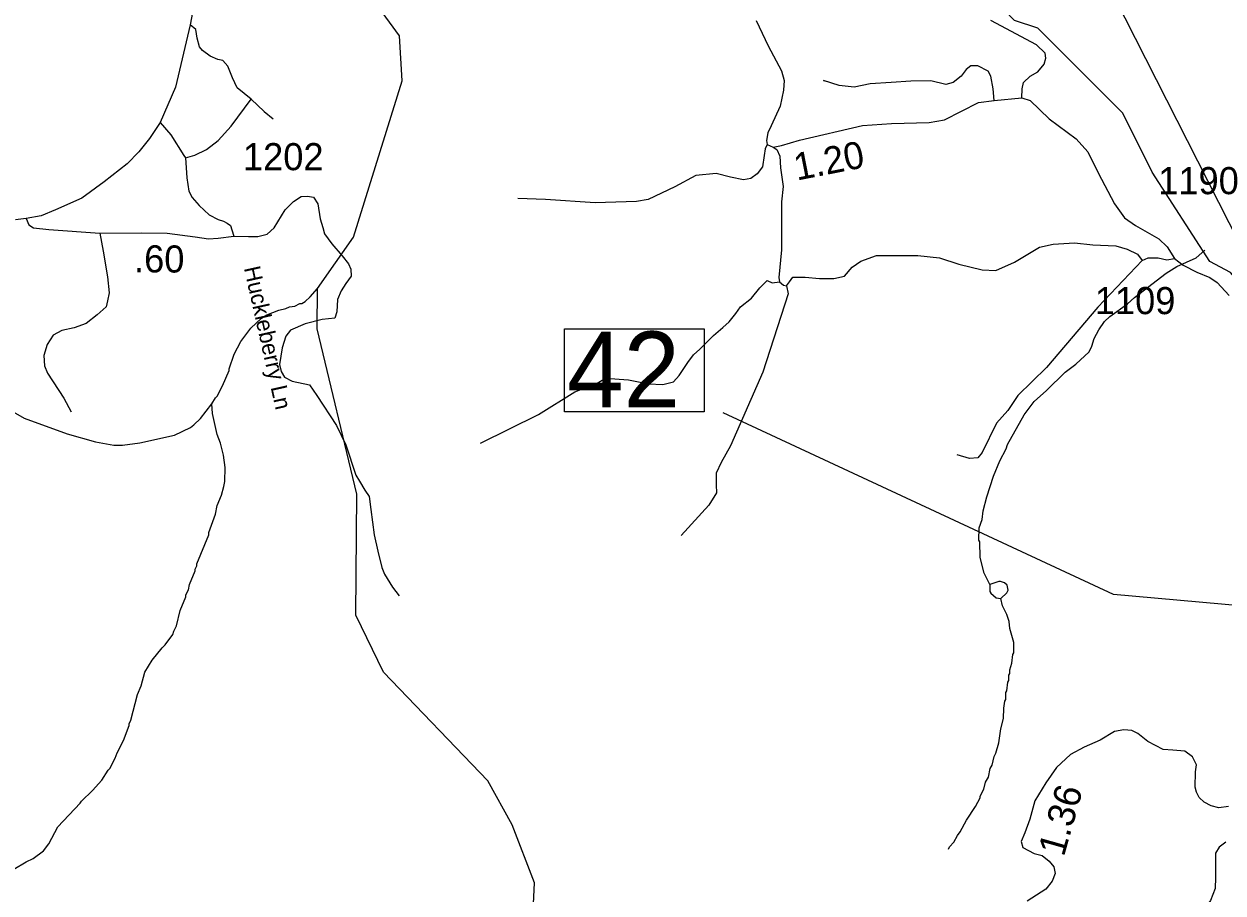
# Model space of a CAD drawing. Extents: x 1248224 to 1454986, y 825081 to 985870.
# Drawn here: x 1349562 to 1355092, y 850677 to 854684 of the extents above; entities that cross this region are included whole.
import ezdxf

# ---------------------------------------------------------------- set-up
doc = ezdxf.new("R2010")
doc.units = 0
for name, color, linetype in [('Exist Hydrographic Creek Single Shore', 7, 'Continuous'), ('Exist Hydrographic Misc Water Feature', 7, 'Continuous'), ('Exist Road Non-System Type 51', 7, 'Continuous'), ('Exist Road Secondary Mileage Hundredths English Label', 7, 'Continuous'), ('Exist Road Secondary Structure Standard Bridge Number Label', 7, 'Continuous'), ('Exist Road Secondary Type 41 Attributed', 7, 'Continuous'), ('Exist Road Secondary Type 51 Attributed', 7, 'Continuous'), ('Exist Road Secondary Type 51 Label', 7, 'Continuous'), ('Exist Road Secondary Type 51 Number Label', 7, 'Continuous')]:
    doc.layers.add(name, color=color, linetype=linetype)

msp = doc.modelspace()

# ---------------------------------------------------------------- linework, layer by layer
at = {"layer": 'Exist Hydrographic Creek Single Shore'}
msp.add_lwpolyline([(1355236.2, 853411.9), (1355127.2, 853537.3), (1355031.4, 853588.9), (1354765.5, 854001.3), (1354629.4, 854273.3), (1354237.4, 854665.2), (1354130.4, 854700.2), (1354081.4, 854750.4), (1354083.4, 854852.1), (1353903.4, 854990.3), (1353765.4, 855167.1), (1353601.4, 855305), (1353497.3, 855582.2), (1353427.9, 855911.2), (1353475.4, 856284.1), (1353588.6, 856393.7), (1353464.7, 856424.9), (1353212.7, 856728.3), (1352949.6, 857225.5), (1352872.2, 857635)], dxfattribs=at)
at = {"layer": 'Exist Hydrographic Misc Water Feature'}
for points in [[(1351884.4, 850047.6), (1351916.4, 850723.3), (1351813.4, 850991.2), (1351701.4, 851193.7), (1351220.4, 851695.8), (1351092.4, 851957.7), (1351096.4, 852515.7), (1350913.4, 853277.7), (1350915.1, 853464), (1351081.4, 853701.1), (1351305.3, 854422.1), (1351293.3, 854629.2), (1351034.4, 854985.6), (1350962.4, 855128.2), (1350783.4, 855309.1), (1350727.4, 855418.5), (1350737.3, 855526.7), (1350815.4, 855640.1), (1351146.3, 855899.3), (1351181.4, 855984), (1351097.3, 856350), (1351009.3, 856502.8), (1350790.3, 856776.4), (1350622.3, 857078.5)], [(1354015.9, 852099.1), (1353991.1, 852151.6), (1353972.7, 852224), (1353970.4, 852296.1), (1353966.6, 852304.2), (1353967.8, 852360.1), (1353980.7, 852399.8), (1353985.7, 852439.7), (1354003.1, 852503.3), (1354033.2, 852598.6), (1354062.9, 852669.8), (1354092.2, 852725.1), (1354098.5, 852745), (1354175.7, 852881.1), (1354221.2, 852944), (1354278.3, 852994.7), (1354364.2, 853078.6), (1354413.1, 853115.5), (1354474.4, 853171.9), (1354486.9, 853197.7), (1354497.8, 853233.4), (1354518.7, 853272.9), (1354545.6, 853312.2), (1354570.1, 853335.7), (1354651.5, 853393.7), (1354684.1, 853422.9), (1354830.7, 853535.4), (1354879.4, 853566.3), (1354968.4, 853606.1), (1355008.7, 853640.3)], [(1350427.4, 852932.2), (1350444.5, 852960), (1350452.7, 852967.8), (1350477.8, 853015.2), (1350507.5, 853086.4), (1350507.7, 853094.4), (1350531.2, 853161.9), (1350562.4, 853219.1), (1350607.9, 853282), (1350657, 853326.9), (1350681.3, 853342.3), (1350737.8, 853364.9), (1350769.9, 853372.2), (1350786.1, 853379.8), (1350810.2, 853383.2), (1350834.5, 853394.6), (1350842.5, 853394.4), (1350858.7, 853404.1), (1350881.2, 853425.5), (1350915.1, 853464)], [(1349142.7, 853012.3), (1349201.9, 853031.5), (1349243.9, 853032.6), (1349287.8, 853027.5), (1349333.4, 853010.4), (1349396.7, 852976.9), (1349471.4, 852919.1), (1349562.3, 852867), (1349760.7, 852794.3), (1349891.8, 852757.2), (1349975.5, 852741.2), (1350015.5, 852742.2), (1350095.7, 852752.3), (1350256.6, 852788.4), (1350329.4, 852822.7), (1350345.8, 852836.3), (1350376.4, 852865.6), (1350427.4, 852932.2)], [(1349515, 850786.4), (1349571.8, 850821), (1349604.2, 850836.2), (1349651.1, 850871.2), (1349675.8, 850904.5), (1349717.5, 850981.5), (1349820, 851091.1), (1349826.3, 851100.9), (1349877.3, 851149.7), (1349920.5, 851196.7), (1349949.5, 851244), (1349957.7, 851251.8), (1349982.8, 851299.2), (1349991.4, 851323), (1350020.7, 851380.2), (1350046.2, 851449.7), (1350046.4, 851457.7), (1350054.8, 851473.4), (1350085.5, 851592.7), (1350102.4, 851632.3), (1350119.8, 851695.9), (1350153.1, 851751.1), (1350198.4, 851808), (1350212.7, 851821.6), (1350247.8, 851868.8), (1350252.2, 851884.7), (1350264.7, 851908.4), (1350282.3, 851980), (1350307.7, 852043.3), (1350308, 852051.3), (1350320.5, 852075), (1350325, 852098.9), (1350350.5, 852162.3), (1350350.6, 852170.3), (1350359, 852186.1), (1350359.2, 852194.1), (1350414.3, 852328.8), (1350414.5, 852338.8), (1350444.4, 852424), (1350453.3, 852463.8), (1350472.4, 852511.4), (1350483.3, 852551.1), (1350487.9, 852575), (1350489.3, 852639), (1350482.6, 852695.1), (1350467.8, 852751.4), (1350452.7, 852791.8), (1350430.9, 852888.3), (1350427.4, 852932.2)], [(1354067.7, 852035), (1354095.1, 852061.1), (1354101.3, 852073), (1354095.9, 852097.1), (1354084.1, 852107.4), (1354066.3, 852113.8), (1354058.3, 852114), (1354015.9, 852099.1)], [(1354015.9, 852099.1), (1354017.2, 852067), (1354021, 852058.9), (1354046.6, 852038.3), (1354067.7, 852035)], [(1353826.2, 850879.7), (1353830.4, 850889.6), (1353850.9, 850911.1), (1353867.7, 850942.7), (1353880.1, 850958.4), (1353909.3, 851013.7), (1353950.7, 851076.7), (1353971.6, 851116.2), (1353971.8, 851124.2), (1353988.5, 851155.8), (1353997.3, 851187.6), (1354009.8, 851211.3), (1354018.7, 851251.1), (1354027.1, 851266.9), (1354036, 851306.6), (1354044.3, 851322.4), (1354057.4, 851370.2), (1354066.9, 851433.9), (1354080, 851481.6), (1354081, 851529.5), (1354085.7, 851561.4), (1354089.9, 851569.3), (1354090.7, 851601.3), (1354094.9, 851609.2), (1354099.8, 851649.1), (1354104, 851657), (1354104.5, 851681), (1354108.7, 851688.9), (1354109.1, 851706.8), (1354117.7, 851736.6), (1354122.6, 851776.5), (1354126.8, 851784.4), (1354127.9, 851832.4), (1354109.4, 851896.8), (1354106.1, 851928.9), (1354094.9, 851961.2), (1354075.8, 852001.6), (1354067.7, 852035)]]:
    msp.add_lwpolyline(points, dxfattribs=at)
at = {"layer": 'Exist Road Non-System Type 51'}
for points in [[(1350609.3, 854337.4), (1350544.3, 854389.9), (1350523.7, 854435.6), (1350502, 854489.2), (1350478.1, 854515.5), (1350455.3, 854520.1), (1350419.9, 854536), (1350385.7, 854562.3), (1350370.9, 854577.8), (1350360.7, 854618.9), (1350353.8, 854657.7), (1350327.7, 854679.7)], [(1354164.3, 854343.9), (1354165.7, 854385.3), (1354171.5, 854414.1), (1354203.2, 854443), (1354237.8, 854463.2), (1354266.6, 854497.8), (1354275.2, 854526.7), (1354272.4, 854549.7), (1354232, 854587.2), (1354021.6, 854699.7)], [(1354036, 854331), (1354032.1, 854384.8), (1354020.6, 854442.5), (1354009.1, 854465.6), (1353961, 854490.6), (1353928.4, 854490.6), (1353907.2, 854473.3), (1353884.2, 854442.5), (1353847.6, 854413.7), (1353813, 854404.1), (1353743.9, 854421.4), (1353651.6, 854419.4), (1353561.3, 854413.7), (1353465.2, 854407.9), (1353390.3, 854392.5), (1353321.1, 854400.2), (1353250, 854423.3), (1353255.7, 854421.4)], [(1350307, 854066.2), (1350350.3, 854078.2), (1350403.9, 854105.6), (1350457.6, 854146.7), (1350516.9, 854213), (1350609.3, 854337.4)], [(1350609.3, 854337.4), (1350669.7, 854280.3), (1350710.8, 854247.2)], [(1350190.2, 854229.6), (1350238.5, 854172.4), (1350299, 854077.6), (1350307, 854066.2)], [(1352990.3, 854128.3), (1352980.3, 854107.6), (1352976.5, 854076.8), (1352968.8, 854024.9), (1352943.8, 853992.2), (1352915, 853971.1), (1352880.4, 853965.3), (1352820.8, 853976.8), (1352753.6, 853994.1), (1352661.3, 853984.5), (1352563.3, 853932.6), (1352440.3, 853874.9), (1352386.5, 853865.3), (1352196.2, 853859.5), (1351967.6, 853874.9), (1351839.3, 853878.8)], [(1353016.7, 854115.8), (1353034.2, 854105.7), (1353047.6, 854075), (1353051.5, 854021.1), (1353063, 853934.6), (1353055.3, 853863.4), (1353055.3, 853642.2), (1353043.8, 853515.3), (1353045.7, 853495.2), (1353065, 853479.8), (1353078.4, 853475.9), (1353086.1, 853439.4), (1352968.9, 853077.8), (1352820.9, 852739.3), (1352776.9, 852661.3), (1352753.8, 852613.2), (1352753.8, 852559.3), (1352755.7, 852522.8), (1352721.1, 852465.1), (1352592.4, 852324.7)], [(1350307, 854066.2), (1350312.7, 853974.9), (1350321.8, 853913.3), (1350337.8, 853883.6), (1350369.7, 853847), (1350416.5, 853803.7), (1350457.6, 853783.1), (1350481.5, 853775.1), (1350498.6, 853766), (1350514.6, 853754.6), (1350520.3, 853735.2), (1350529.2, 853705.7)], [(1349911.4, 853718.9), (1349927.5, 853637), (1349947.2, 853517.3), (1349954.2, 853444), (1349947.2, 853407.4), (1349940.1, 853379.3), (1349899.3, 853342.7), (1349848.7, 853303.2), (1349792.4, 853283.5), (1349736.1, 853270.8), (1349696.7, 853249.7), (1349668.6, 853206.1), (1349653.1, 853155.4), (1349655.9, 853107.5), (1349670, 853073.7), (1349746, 852958.2), (1349779.7, 852895.7)], [(1353078.4, 853475.9), (1353092.9, 853495.7), (1353107.3, 853515.9), (1353165, 853515.9), (1353231.3, 853510.1), (1353297.6, 853510.1), (1353346.6, 853521.7), (1353381.2, 853562.1), (1353421.5, 853590.9), (1353493.6, 853616.9), (1353571.4, 853616.9), (1353683.8, 853616.9), (1353784.7, 853605.3), (1353874.1, 853576.5), (1353980.8, 853550.5), (1354044.2, 853547.7), (1354130.7, 853585.2), (1354246, 853654.4), (1354309.4, 853668.8), (1354407.4, 853674.6), (1354491, 853665.9), (1354597.7, 853660.2), (1354649.5, 853645.7), (1354698.5, 853622.7), (1354718.7, 853593.8)], [(1354718.7, 853593.8), (1354746.8, 853605.5), (1354793, 853605.5), (1354833.3, 853596.9), (1354867.8, 853603.2)], [(1354718.7, 853593.8), (1354514.1, 853377.5), (1354277.7, 853100.5), (1354145.1, 852970.7), (1354099, 852901.5), (1354047.1, 852843.8), (1353980.8, 852708.2), (1353960.7, 852682.8), (1353923.2, 852680), (1353865.5, 852697.3)], [(1351666.7, 852751.1), (1351934.8, 852883.8), (1352102, 852987.7), (1352205.8, 853028.1), (1352243.3, 853051.2), (1352349.9, 853042.5), (1352442.2, 853025.2), (1352508.5, 853022.3), (1352557.5, 853033.9), (1352583.4, 853062.7), (1352623.8, 853123.3), (1352649.7, 853157.9), (1352678.5, 853183.9), (1352742, 853247.3), (1352785.2, 853284.8), (1352814, 853310.8), (1352845.7, 853348.3), (1352865.9, 853380), (1352917.8, 853420.4), (1352955.3, 853466.6), (1352989.9, 853501.2), (1353012.9, 853489.6), (1353045.7, 853495.2)], [(1351134.4, 852534.6), (1351153.6, 852505.4), (1351161.3, 852445.7), (1351176.7, 852328.4), (1351194, 852253.4), (1351211.7, 852177.9), (1351225.1, 852147.2), (1351261.6, 852087.5), (1351292.4, 852047.2)]]:
    msp.add_lwpolyline(points, dxfattribs=at)
at = {"layer": 'Exist Road Secondary Structure Standard Bridge Number Label'}
msp.add_line((1355294.6, 853422.2), (1354064.6, 855847.7), dxfattribs=at)
msp.add_lwpolyline([(1352054.4, 853278.3), (1352698.6, 853278.3), (1352698.6, 852896), (1352054.4, 852896)], close=True, dxfattribs=at)
msp.add_lwpolyline([(1356407.1, 851889.8), (1354587.4, 852053.5), (1352786, 852890.6)], dxfattribs=at)
at = {"layer": 'Exist Road Secondary Type 41 Attributed'}
msp.add_lwpolyline([(1350939.4, 853744.8), (1350947.9, 853717), (1350981.8, 853669.8), (1351029, 853615.1), (1351059.2, 853577.3), (1351068.6, 853552.8), (1351070.5, 853520.7), (1351046, 853486.7), (1351025.2, 853452.8), (1351008.2, 853413.1), (1351004.5, 853356.5), (1350995, 853328.2), (1350936.6, 853320.6), (1350859.2, 853301.8), (1350791.4, 853271.6), (1350768.8, 853244.3), (1350751.8, 853191.4), (1350740.5, 853114), (1350748, 853082), (1350763.1, 853055.5), (1350798.9, 853036.7), (1350878.2, 853019.7), (1350912.1, 852970.6), (1351002.6, 852832.8), (1351045.6, 852743.4), (1351092.8, 852603.7), (1351108.5, 852576), (1351134.4, 852534.6)], dxfattribs=at)
at = {"layer": 'Exist Road Secondary Type 51 Attributed'}
for points in [[(1350350.3, 854794.9), (1350327.7, 854679.7), (1350259.8, 854392.8), (1350190.2, 854229.6), (1350141.1, 854155.9), (1350092.1, 854093.7), (1350037.4, 854038.9), (1349931.8, 853955.9), (1349828.1, 853880.4), (1349707.3, 853827.5), (1349640.1, 853799.7), (1349572.2, 853786.5)], [(1352939.1, 854699.9), (1352994.7, 854583.1), (1353055.4, 854468.5), (1353067.9, 854423.9), (1353065.1, 854379.4), (1353049.9, 854304.3), (1353008.1, 854213.9), (1352993.1, 854181.2), (1352986.1, 854146.4), (1352990.3, 854128.3), (1353016.7, 854115.8), (1353055.6, 854122.8), (1353139.1, 854147.8), (1353429.6, 854216), (1353562.3, 854225.7), (1353737.5, 854229.8), (1353807, 854242.4), (1353964.1, 854321.7), (1354036, 854331), (1354164.3, 854343.9), (1354202.5, 854331.5), (1354290.1, 854246.6), (1354415.2, 854154.8), (1354468, 854095), (1354516.7, 853997.6), (1354591.8, 853854.3), (1354637.1, 853789.6), (1354688.5, 853754.9), (1354796.9, 853693.6), (1354834.5, 853656.1), (1354867.8, 853603.2), (1354908.1, 853571.2), (1354972.1, 853539.2), (1355031.9, 853515.6), (1355065.2, 853491.9), (1355120.8, 853432.1)], [(1349572.2, 853786.5), (1349583.3, 853758.5), (1349605.9, 853743.4), (1349675.7, 853735.8), (1349911.4, 853718.9), (1350105.7, 853720.7), (1350222.6, 853718.9), (1350350.9, 853701.9), (1350412.3, 853692.5), (1350457.5, 853696.2), (1350529.2, 853705.7), (1350597.1, 853703.8), (1350640.5, 853703.8), (1350683.9, 853715.1), (1350715.9, 853743.4), (1350766.8, 853826.5), (1350804.6, 853866.1), (1350840.4, 853888.8), (1350868.7, 853890.7), (1350897, 853885), (1350917.7, 853854.8), (1350927.1, 853785), (1350939.4, 853744.8)], [(1349572.2, 853786.5), (1349521.8, 853780.9)], [(1355117.8, 851075.4), (1355073.5, 851070.5), (1355037.5, 851078.6), (1355004.7, 851096.7), (1354981.7, 851118), (1354970.3, 851142.6), (1354963.7, 851165.5), (1354965.4, 851236), (1354969.5, 851268.8), (1354951.4, 851304.8), (1354915.4, 851331.1), (1354861.3, 851336), (1354815.4, 851339.3), (1354745.7, 851375.4), (1354699, 851413), (1354671.1, 851426.1), (1354635.1, 851429.4), (1354591.9, 851421.4), (1354526, 851381.4), (1354452.2, 851349.5), (1354388.3, 851315.5), (1354324.4, 851255.5), (1354274.5, 851185.6), (1354224.6, 851101.7), (1354200.6, 851017.1), (1354178.7, 850955.2), (1354160.7, 850915.2), (1354168.7, 850887.2), (1354220.6, 850859.3), (1354258.5, 850849.3), (1354290.5, 850823.3), (1354312.4, 850797.3), (1354318.4, 850767.4), (1354304.5, 850731.4), (1354274.5, 850695.4), (1354188.7, 850639.5)], [(1355105.5, 850911.5), (1355074.4, 850888.5), (1355057.8, 850860.8), (1355058, 850808.2), (1355058, 850749.2), (1355056.3, 850698.4), (1355033.9, 850642.6), (1354897.2, 850449.2), (1354878.6, 850422.6), (1354806.8, 850350.8), (1354600.7, 850189.8), (1354538.5, 850138.3), (1354514.6, 850114.3), (1354468.1, 850041.1), (1354432.2, 849986.6), (1354379, 849918.7), (1354376.5, 849890), (1354392.4, 849761), (1354401.7, 849675.8), (1354403.1, 849642.6), (1354389.8, 849605.3), (1354369.8, 849573.4), (1354367.9, 849554.9)]]:
    msp.add_lwpolyline(points, dxfattribs=at)

# ---------------------------------------------------------------- texts
at = {"layer": 'Exist Road Secondary Mileage Hundredths English Label'}
for s, rotation, p in [('1.20', 11.0837, (1353126.3, 853961.5)), ('.60', 359.6249, (1350068.9, 853539)), ('1.36', 74.2005, (1354357.9, 850840.8))]:
    msp.add_text(s, height=125, rotation=rotation, dxfattribs=at).set_placement(p)
at = {"layer": 'Exist Road Secondary Structure Standard Bridge Number Label'}
msp.add_text('42', height=350, dxfattribs=at).set_placement((1352067, 852915.7))
at = {"layer": 'Exist Road Secondary Type 51 Label'}
msp.add_text('Huckleberry Ln', height=75, rotation=282.6355, dxfattribs=at).set_placement((1350575.8, 853558.6))
at = {"layer": 'Exist Road Secondary Type 51 Number Label'}
for s, p in [('1202', (1350571.6, 854009.6)), ('1190', (1354793.3, 853899)), ('1109', (1354500.7, 853345.9))]:
    msp.add_text(s, height=125, dxfattribs=at).set_placement(p)

doc.saveas('drawing.dxf')
